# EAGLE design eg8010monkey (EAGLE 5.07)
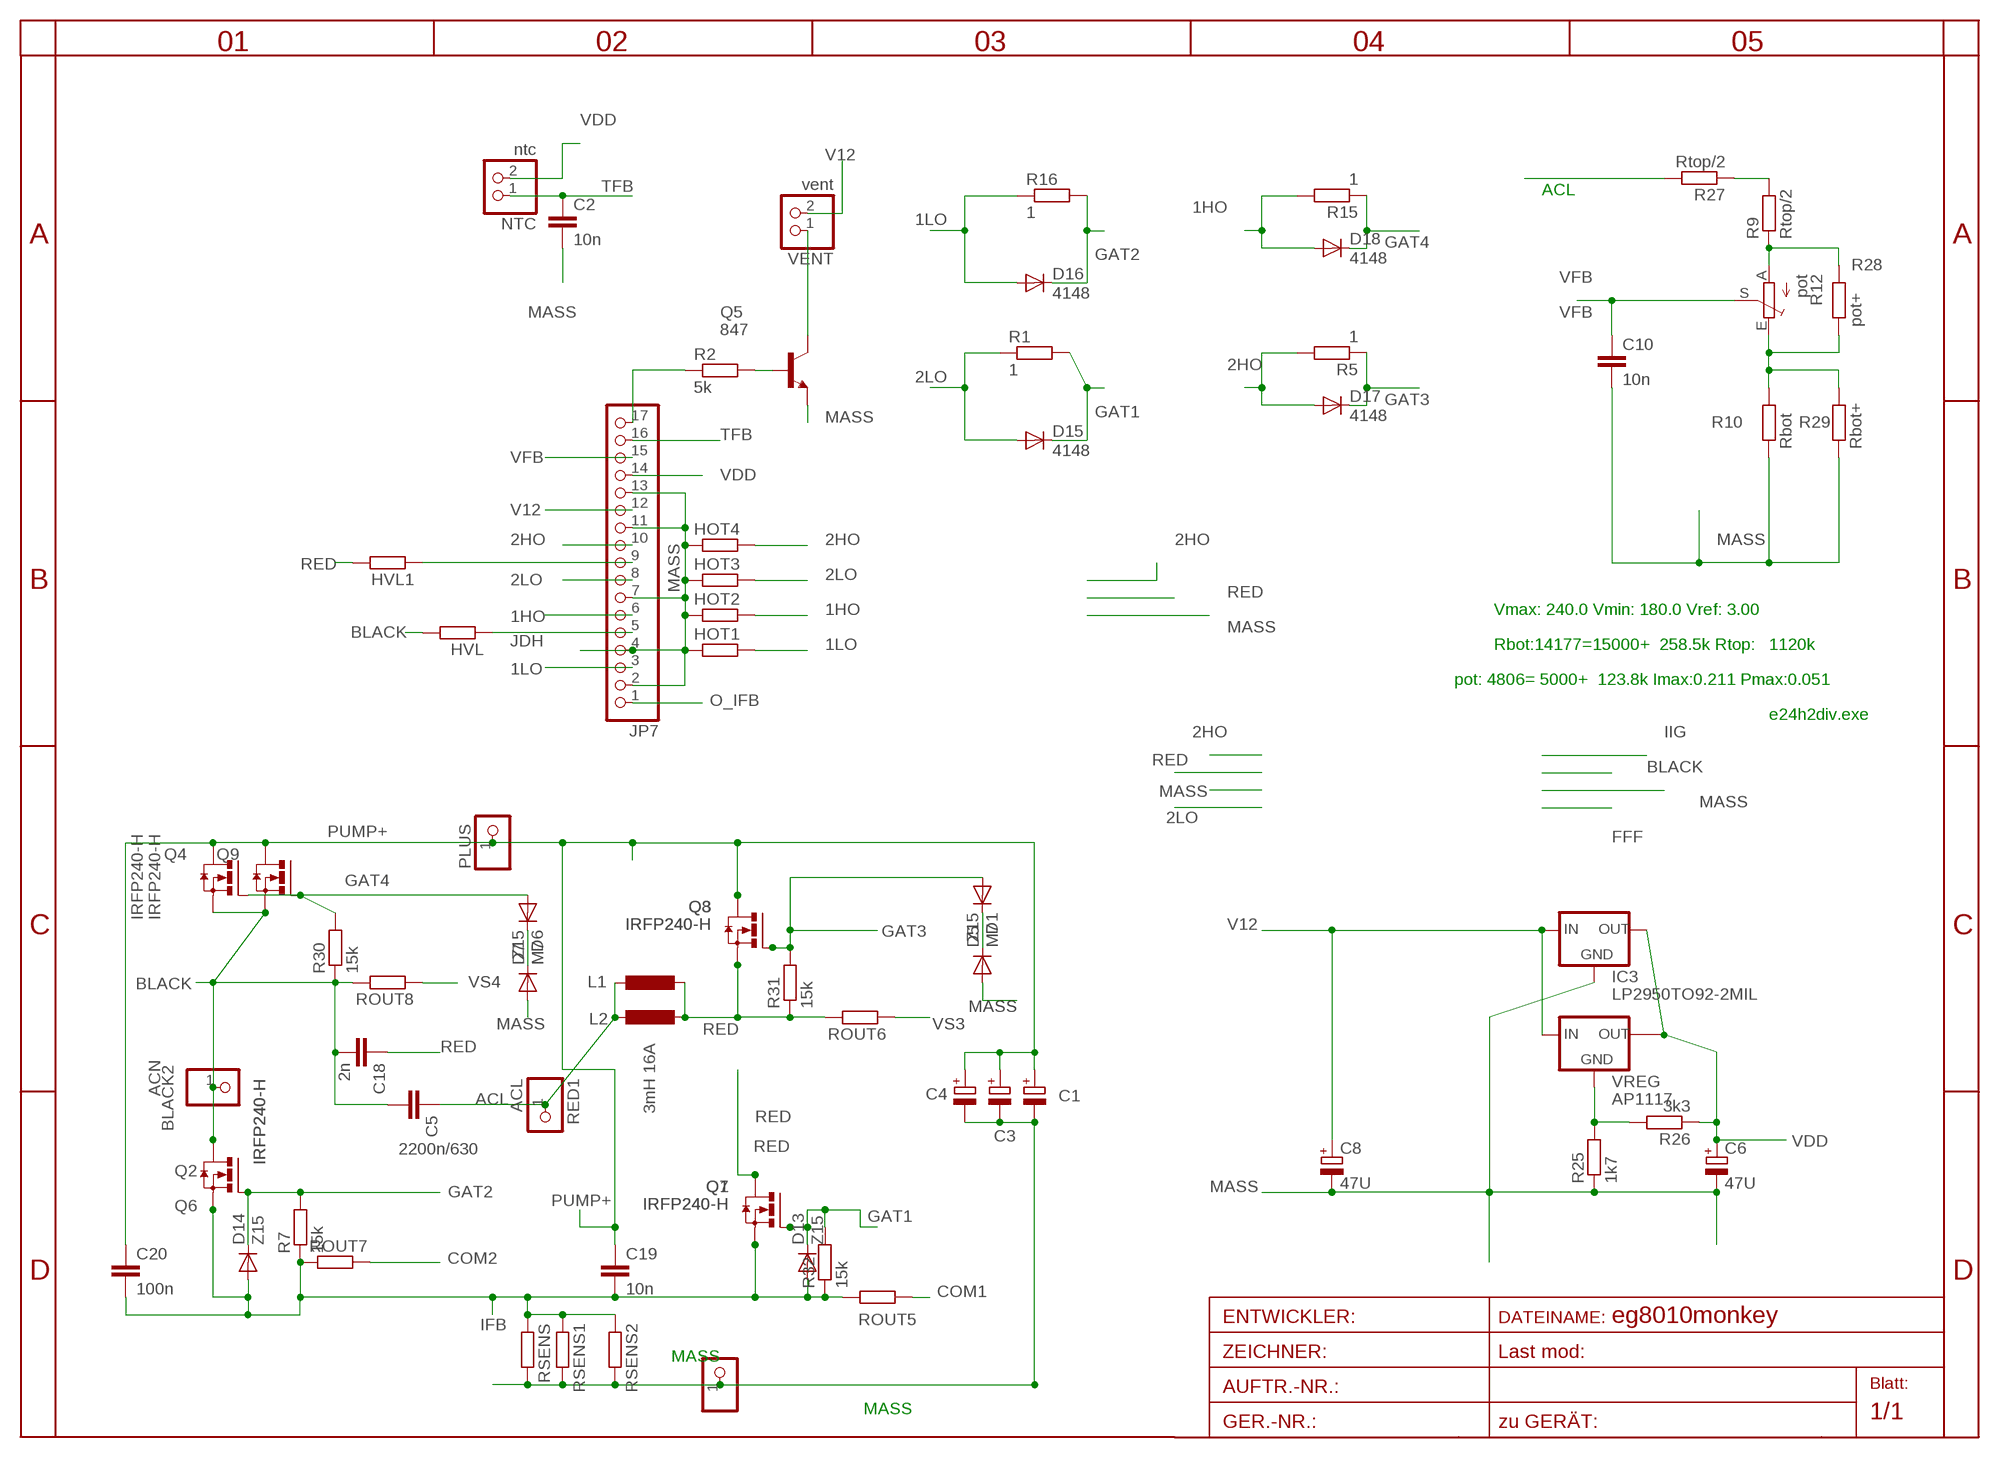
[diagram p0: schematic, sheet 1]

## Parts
BLACK2  ACN  PINHD-1X12MM3  [1X2MM3]
C1  CPOL-EUE5-13  [E5-13]
C2  10n  C-EUC0805  [C0805]
C3  CPOL-EUE5-13  [E5-13]
C4  CPOL-EUE5-13  [E5-13]
C5  2200n/630  C-EU275-173X316  [C275-173X316]
C6  47U  CPOL-EUSMCA  [SMC_A]
C8  47U  CPOL-EUSMCA  [SMC_A]
C10  10n  C-EUC0805  [C0805]
C18  2n  C-EU050-024X044  [C050-024X044]
C19  10n  C-EU050-024X044  [C050-024X044]
C20  100n  C-EU050-024X044  [C050-024X044]
D1  Z15  DIODE-MINIMELF  [MINIMELF]
D5  M7  DIODE-SMA-DO214  [SMA-DO214AC]
D6  Z15  DIODE-MINIMELF  [MINIMELF]
D7  M7  DIODE-SMA-DO214  [SMA-DO214AC]
D13  Z15  DIODE-MINIMELF  [MINIMELF]
D14  Z15  DIODE-MINIMELF  [MINIMELF]
D15  4148  DIODE-MINIMELF  [MINIMELF]
D16  4148  DIODE-MINIMELF  [MINIMELF]
D17  4148  DIODE-MINIMELF  [MINIMELF]
D18  4148  DIODE-MINIMELF  [MINIMELF]
HOT1  R-EU_R0805  [R0805]
HOT2  R-EU_R0805  [R0805]
HOT3  R-EU_R0805  [R0805]
HOT4  R-EU_R0805  [R0805]
HVL  R-EU_R1005  [R1005]
HVL1  R-EU_R1005  [R1005]
IC3  LP2950TO92-2MIL  [TO92-2MIL]
JP7  PINHD-1X17  [1X17]
L1  L-EU4.13  [0204/13]
L2  3mH 16A  L-EURNG  [RING]
MINUS  PINHD-1X12MM3  [1X2MM3]
NTC  ntc  PINHD-1X2STR  [1X02]
PLUS  PINHD-1X12MM3  [1X2MM3]
Q1  IRFP240-H  [TO247BH]
Q2  IRFP240-H  [TO247BH]
Q3  IRFP240-H  [TO247BH]
Q4  IRFP240-H  [TO247BH]
Q5  847  BC847SMD  [SOT23]
Q6  IRFP240-H  [TO247BH]
Q7  IRFP240-H  [TO247BH]
Q8  IRFP240-H  [TO247BH]
Q9  IRFP240-H  [TO247BH]
R1  1  R-EU_R2512  [R2512]
R2  5k  R-EU_R0805  [R0805]
R5  1  R-EU_R2512  [R2512]
R7  15k  R-EU_R1206  [R1206]
R9  Rtop/2  R-EU_R1206  [R1206]
R10  Rbot  R-EU_R0805  [R0805]
R12  pot  TRIM_EU-B64Y  [B64Y]
R15  1  R-EU_R2512  [R2512]
R16  1  R-EU_R2512  [R2512]
R25  1k7  R-EU_R0805  [R0805]
R26  3k3  R-EU_R0805  [R0805]
R27  Rtop/2  R-EU_R1206  [R1206]
R28  pot+  R-EU_R0805  [R0805]
R29  Rbot+  R-EU_R0805  [R0805]
R30  15k  R-EU_R1206  [R1206]
R31  15k  R-EU_R1206  [R1206]
R32  15k  R-EU_R1206  [R1206]
RED1  ACL  PINHD-1X12MM3  [1X2MM3]
ROUT5  R-EU_R2512  [R2512]
ROUT6  R-EU_R2512  [R2512]
ROUT7  R-EU_R2512  [R2512]
ROUT8  R-EU_R2512  [R2512]
RSENS  R-EU_WIRE  [WIRE]
RSENS1  R-EU_WIRE  [WIRE]
RSENS2  R-EU_WIRE  [WIRE]
VENT  vent  PINHD-1X2STR  [1X02]
VREG  AP1117  [SOT223]

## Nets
1HO: D18.A HOT2.2 JP7.6 R15.2
1LO: D16.A HOT1.2 JP7.3 R16.1
2HO: D17.A HOT4.2 JP7.10 R5.2
2LO: D15.A HOT3.2 JP7.8 R1.1
ACL: C5.1 L1.1 L2.2 R27.2 RED1.1
BLACK: BLACK2.1 C5.2 C18.2 HVL.2 Q2.D Q4.S Q6.D Q9.S R30.1 ROUT8.2
COM1: ROUT5.1
COM2: ROUT7.2
GAT1: D13.C D15.C Q1.G Q7.G R1.2 R32.2
GAT2: D14.C D16.C Q2.G Q6.G R7.2 R16.2
GAT3: D1.A D17.C Q3.G Q8.G R5.1 R31.2
GAT4: D6.A D18.C Q4.G Q9.G R15.1 R30.2
IFB: C19.2 C20.2 D13.A D14.A Q1.S Q2.S Q6.S Q7.S R7.1 R32.1 ROUT5.2 ROUT7.1 RSENS1.1 RSENS2.1 RSENS.1
JDH: HVL.1 JP7.5
MASS: C1.- C2.2 C3.- C4.- C6.- C8.- C10.2 D5.A D7.A HOT1.1 HOT2.1 HOT3.1 HOT4.1 IC3.2(GND) JP7.2 JP7.4 JP7.7 JP7.11 JP7.13 MINUS.1 Q5.2(E) R10.1 R25.1 R29.1 RSENS1.2 RSENS2.2 RSENS.2
N$1: Q5.3(C) VENT.1
N$2: Q5.1(B) R2.2
N$3: JP7.17 R2.1
N$17: R25.2 R26.2 VREG.1(GND)
N$20: D1.C D5.K(C)
N$23: R9.2 R27.1
N$24: D6.C D7.K(C)
N$29: R10.2 R12.E R28.1 R29.2
N$30: R9.1 R12.A R28.2
O_IFB: JP7.1
PUMP+: C1.+ C3.+ C4.+ C19.1 C20.1 PLUS.1 Q3.D Q4.D Q8.D Q9.D
RED: C18.1 HVL1.2 L1.2 L2.1 Q1.D Q3.S Q7.D Q8.S R31.1 ROUT6.2
TFB: C2.1 JP7.16 NTC.1
V12: C8.+ IC3.3(IN) JP7.12 VENT.2 VREG.3(IN)
VDD: C6.+ IC3.1(OUT) JP7.14 NTC.2 R26.1 VREG.4(TAB)
VFB: C10.1 JP7.15 R12.S
VS3: HVL1.1 JP7.9 ROUT6.1
VS4: ROUT8.1
Unconnected: VREG.2(OUT)

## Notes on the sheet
- Vmax: 240.0 Vmin: 180.0 Vref: 3.00
- Rbot:14177=15000+  258.5k Rtop:   1120k
- pot: 4806= 5000+  123.8k Imax:0.211 Pmax:0.051
- e24h2div.exe

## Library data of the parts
BLACK2 MINUS PLUS RED1 = pinhead:PINHD-1X1: PIN HEADER
C1 C3 C4 C6 C8 = rcl:CPOL-EU: POLARIZED CAPACITOR, European symbol
C2 C5 C10 C18-C20 = rcl:C-EU: CAPACITOR, European symbol
D1 D5-D7 D13-D18 = diode:DIODE-: DIODE
HOT1-HOT4 HVL HVL1 R1 R2 R5 R7 R15 R16 R30-R32 ROUT5-ROUT8 RSENS RSENS1 RSENS2 = rcl:R-EU_: RESISTOR, European symbol
IC3 = v-reg:LP2950?*: Source: http://cache.national.com/ds/LP/LP2950.pdf
JP7 = pinhead:PINHD-1X17: PIN HEADER
L1 L2 = rcl:L-EU: INDUCTOR, European symbol
NTC VENT = pinhead:PINHD-1X2: PIN HEADER
Q1-Q4 Q6-Q9 = transistor-power:IRFP240: HEXFET Power MosFet Source: http://www.irf.com/
Q5 = transistor-npn:BC847*: NPN Transistor
R9 R10 R25-R29 = rcl-2:R-EU_: RESISTOR, European symbol
R12 = pot:TRIM_EU-: POTENTIOMETER
VREG = v-reg:AP1117

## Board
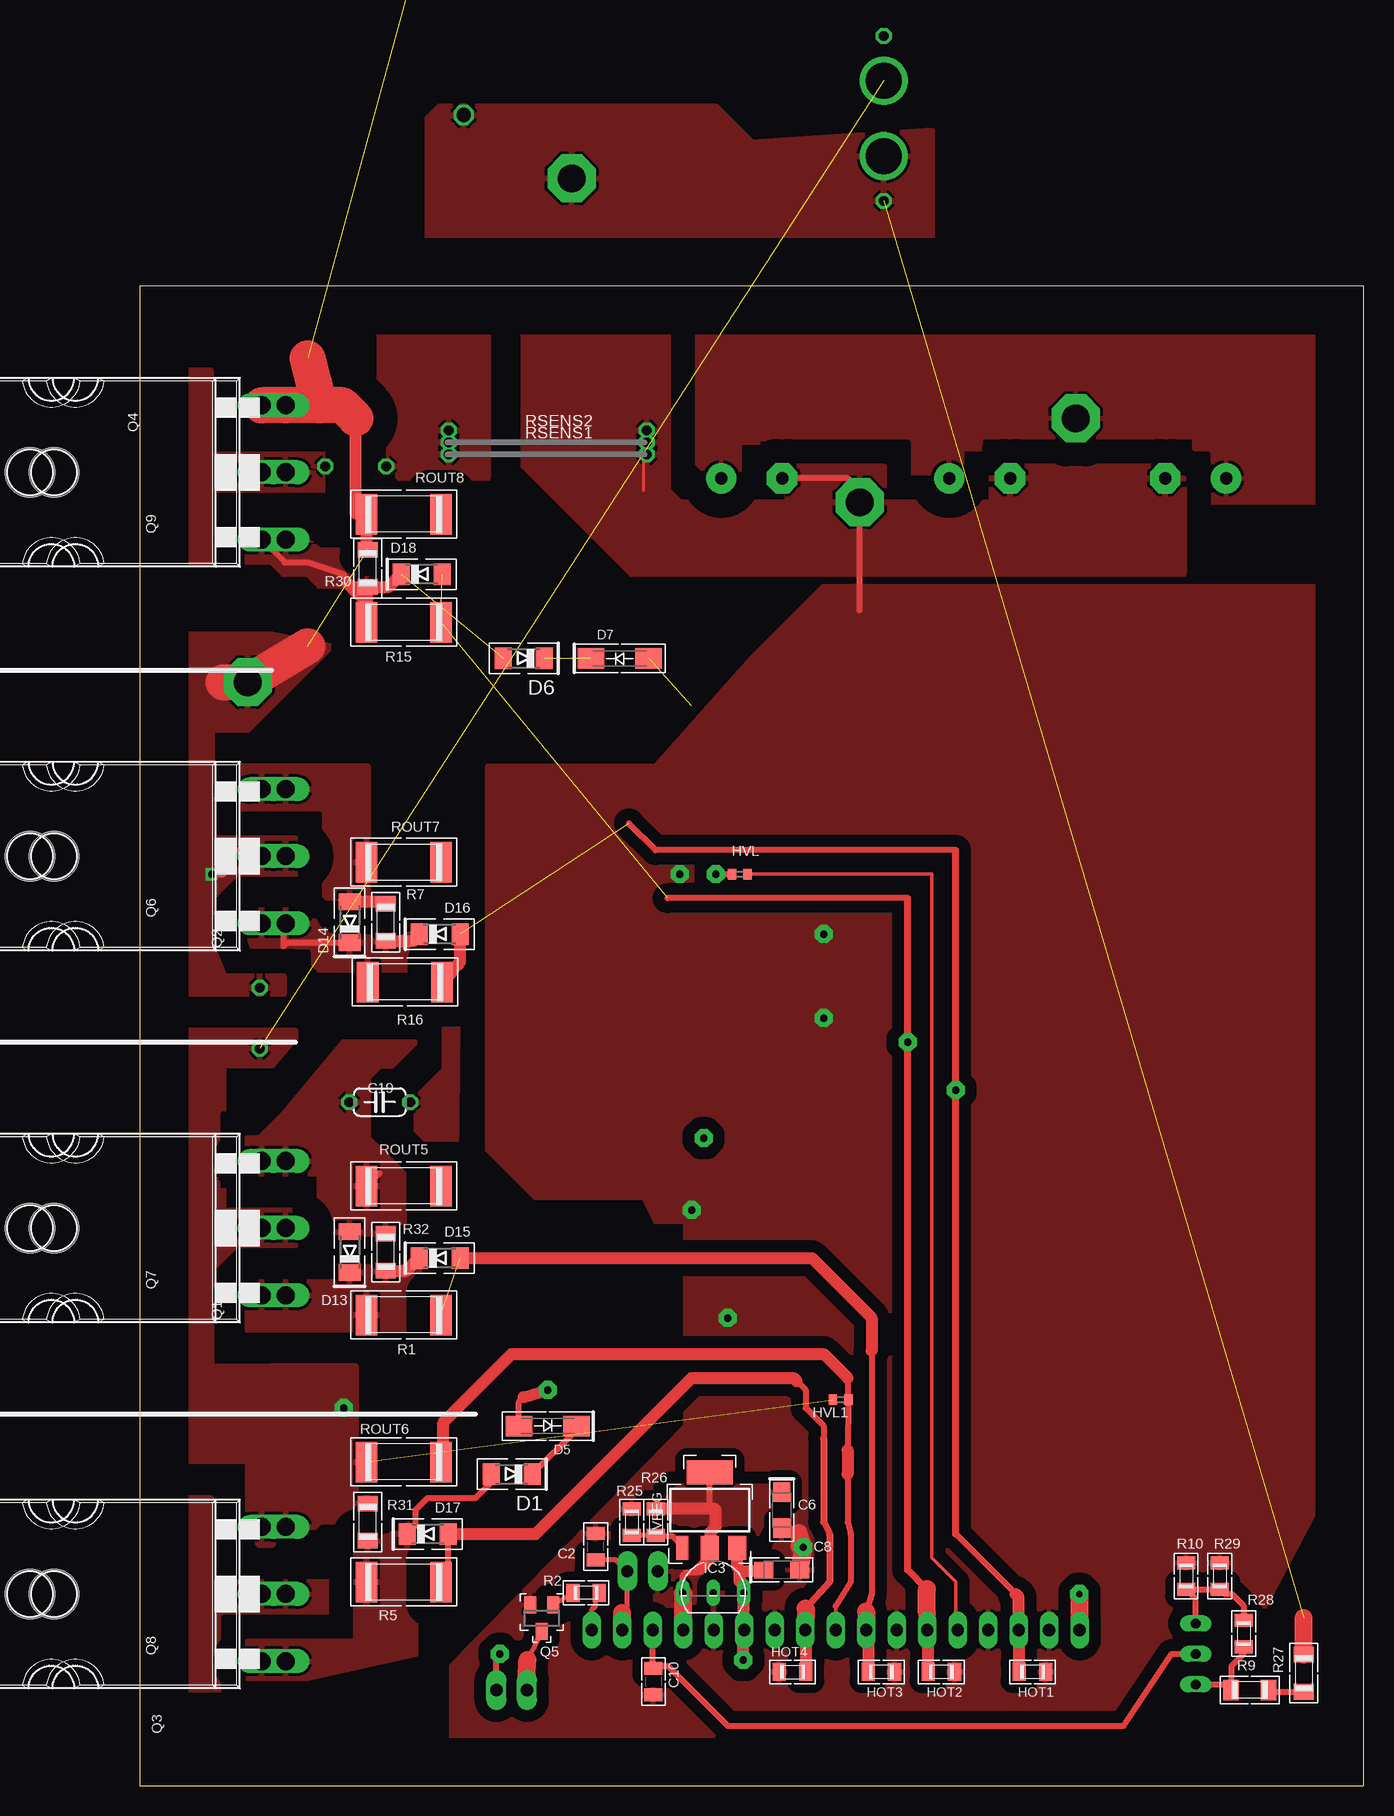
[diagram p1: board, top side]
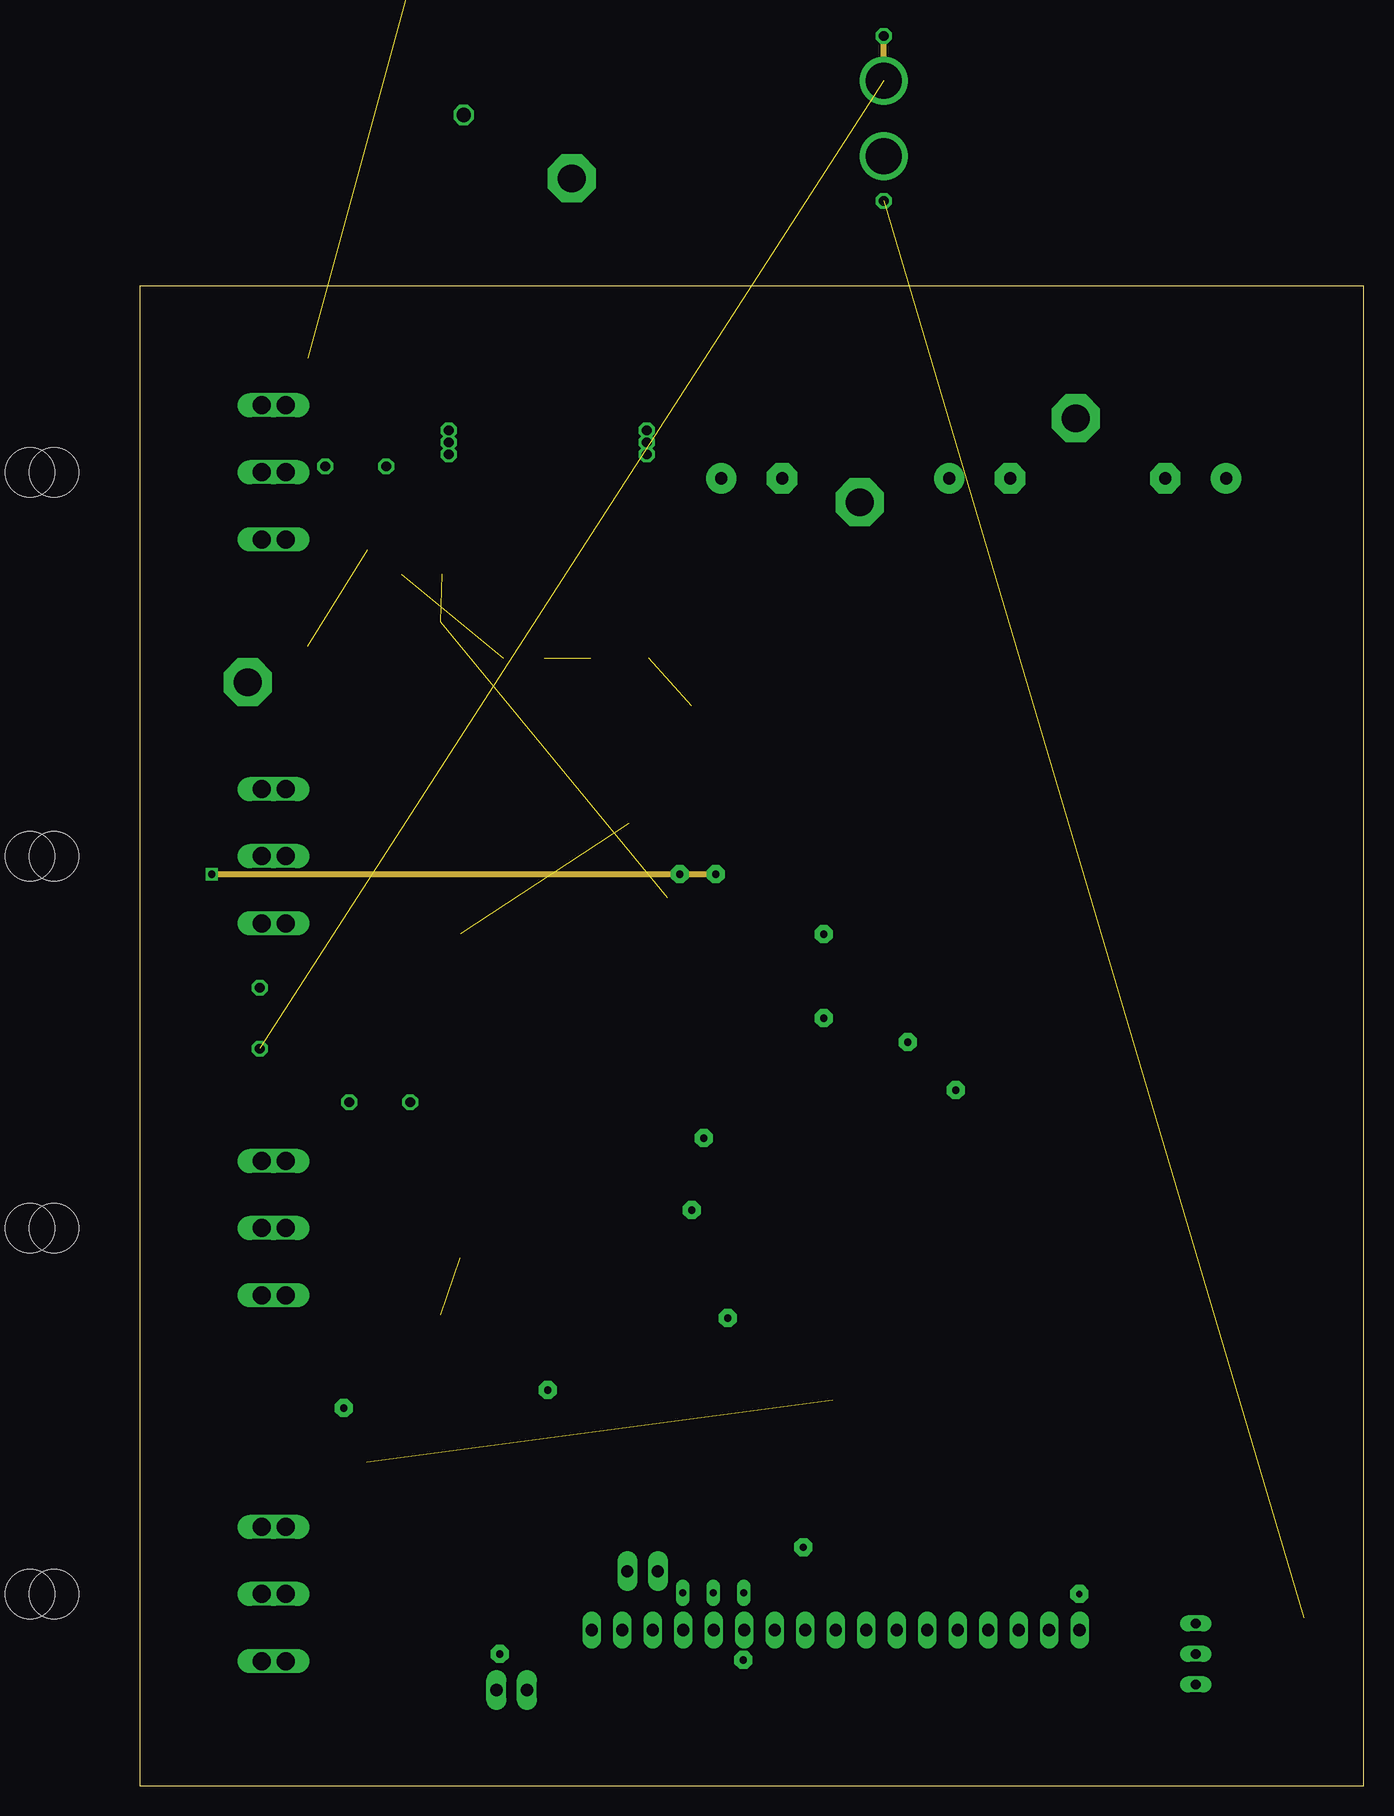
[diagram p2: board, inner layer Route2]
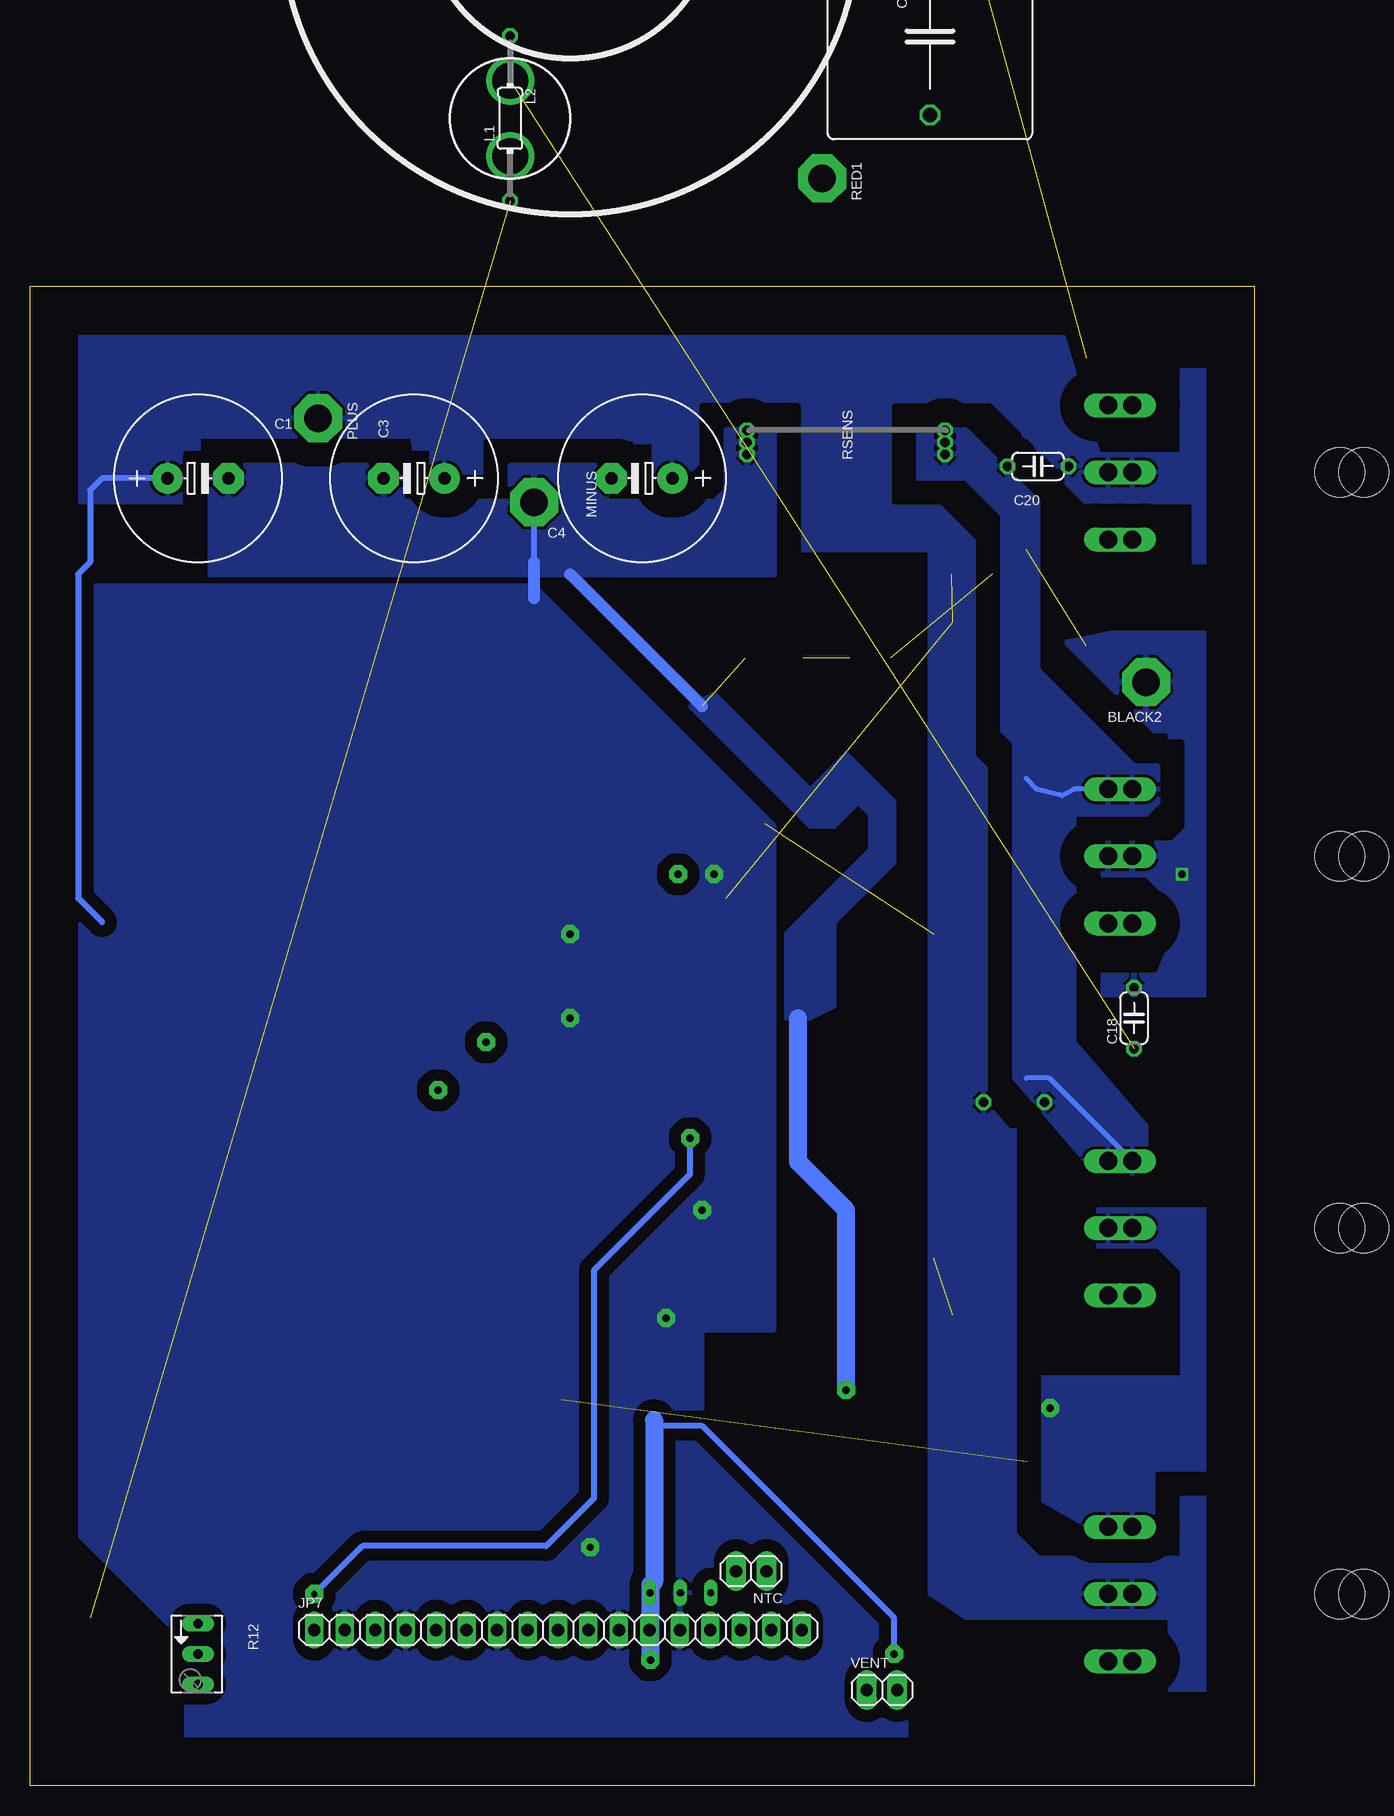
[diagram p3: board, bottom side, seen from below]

Size 102 x 125 mm. Coordinates in mm from the lower left corner, seen from the top.
Outline: 0,0 102,0 102,125 0,125 0,0
Copper layers (1*16): Top 0.035mm / dielectric 1.5mm / Bottom 0.035mm
Design rules "default *": minimum track width 10mil, minimum drill 20mil, track to track 8mil, track to pad 8mil, pad to pad 8mil, via to via 8mil, smd to smd 8mil, copper to edge 4mm, drill to drill 8mil, minimum pad ring 10mil, minimum via ring 8mil, stop-mask expansion 4mil, vias tented up to drill 0mil, thermal gap 10mil

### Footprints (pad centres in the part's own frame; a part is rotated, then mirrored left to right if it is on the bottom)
1X2MM3 = drill 2.3 pad 4 octagon: 1 0,0
E5-13 = drill 1.016 pad 2.54 round: + -2.54,0 | drill 1.016 pad 2.54 octagon: - 2.54,0
C0805 = smd 1.1 x 1.5: 1 -1.1,0; 2 1.1,0
C275-173X316 = drill 1.194 octagon: 1 -13.716,0; 2 13.716,0
SMC_A = smd 1.6 x 1.4: + -1.5,0; - 1.5,0
C050-024X044 = drill 0.813 octagon: 1 -2.54,0; 2 2.54,0
MINIMELF = smd 1.4 x 1.8: A 1.7,0; C -1.7,0
SMA-DO214AC = smd 2.2 x 1.7: A 2.4,0; K -2.4,0
R0805 = smd 1.1 x 1.5: 1 -1.1,0; 2 1.1,0
R1005 = smd 0.7 x 0.9: 1 -0.65,0; 2 0.65,0
TO92-2MIL = drill 0.6 pad 0.813 long: 1 -2.54,0; 2 0,0; 3 2.54,0
1X17 = drill 1.016 long: 1 -20.32,0; 2 -17.78,0; 3 -15.24,0; 4 -12.7,0; 5 -10.16,0; 6 -7.62,0; 7 -5.08,0; 8 -2.54,0; 9 0,0; 10 2.54,0; 11 5.08,0; 12 7.62,0; 13 10.16,0; 14 12.7,0; 15 15.24,0; 16 17.78,0; 17 20.32,0
0204/13 = drill 0.813 octagon: 1 -6.872,0; 2 6.872,0
RING = drill 3 pad 4 round: 1 -3.15,0; 2 3.15,0
1X02 = drill 1.016 pad 1.676 long: 1 -1.27,0; 2 1.27,0
TO247BH = drill 1.499 long: D 0,-10.16; G -5.588,-10.16; S 5.588,-10.16 | hole 4.115: 0,9.144
SOT23 = smd 1 x 1.4: 1 -0.95,-1.1; 2 0.95,-1.1; 3 0,1.1
R2512 = smd 1.8 x 3.4: 1 -3.1,0; 2 3.1,0
R1206 = smd 1.3 x 1.7: 1 -1.55,0; 2 1.55,0
B64Y = drill 0.813 long: A 2.54,0; E -2.54,0; S 0,0
WIRE = drill 0.813 octagon: 1 -8.25,0; 2 8.25,0
SOT223 = smd 1 x 2: 1 -2.3,-3.15 | smd 1.5 x 2: 2 0,-3.15; 3 2.3,-3.15 | smd 3.8 x 2: 4 0,3.15

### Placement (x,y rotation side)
BLACK2  9,92 180 bottom
C1  88,109 0 bottom
C2  38,19.95 90 top
C3  70,109 180 bottom
C4  51,109 180 bottom
C5  not placed on the board
C6  53.5,23 270 top
C8  53.5,18 0 top
C10  42.8,8.7 270 top
C18  10,64 90 bottom
C19  20,57 180 top
C20  18,110 180 bottom
D1  31,26 180 top
D5  34,30 180 top
D6  32,94 180 top
D7  40,94 0 top
D13  17.5,44.5 90 top
D14  17.5,72 90 top
D15  25,44 0 top
D16  25,71 0 top
D17  24,21 0 top
D18  23.5,101 0 top
HOT1  74.4,9.5 180 top
HOT2  66.8,9.5 180 top
HOT3  61.8,9.5 180 top
HOT4  54.4,9.5 0 top
HVL  50,76 180 top
HVL1  58.4,32.2 180 top
IC3  47.8,16.1 0 top
JP7  58,13 0 bottom
L1  62,139 90 bottom  (outside the outline)
L2  62,139 270 bottom  (outside the outline)
MINUS  60,107 270 bottom
NTC  41.9,17.9 180 bottom
PLUS  78,114 270 bottom
Q1  0,46.5 90 top
Q2  0,77.5 90 top
Q3  0,16 90 top
Q4  0,109.5 90 top
Q5  33.5,14 180 top
Q6  2,77.5 90 top
Q7  2,46.5 90 top
Q8  2,16 90 top
Q9  2,109.5 90 top
R1  22,39.25 180 top
R2  37.2,16.1 180 top
R5  22,17 0 top
R7  20.5,72 270 top
R9  92.5,8 0 top
R10  87.2,17.5 270 top
R12  88,11 270 bottom
R15  22,97 0 top
R16  22.1,67 180 top
R25  41,22 270 top
R26  43,22 270 top
R27  97,9.4 90 top
R28  92,12.7 270 top
R29  90,17.5 270 top
R30  19,101.5 270 top
R31  19,22 270 top
R32  20.5,44.5 270 top
RED1  not placed on the board
ROUT5  22,50 180 top
ROUT6  22,27 180 top
ROUT7  22,77 0 top
ROUT8  22,106 180 top
RSENS  34,113 180 bottom
RSENS1  34,111 0 top
RSENS2  34,112 0 top
VENT  31,8 0 bottom
VREG  47.5,23 0 top

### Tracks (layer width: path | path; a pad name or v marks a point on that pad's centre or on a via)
1HO  (via drill 0.6 pad 1.5)  (2 unrouted)
  Top 0.5: 64,74 44,74
  Top 0.6: 65.6,16.4 64,18 v64,62 64,74
  Top 1: 65.6,14.4 JP7.6 65.7,12.92 HOT2.2
  Top 1.5: 65.6,14.4 65.6,16.4
1LO  (via drill 0.6 pad 1.5)  (1 unrouted)
  Top 0.5: 68,78 43,78 40.77,80.23 | 73,16 68,21
  Top 0.6: 68,21 v68,58 68,78
  Top 1: 73,16 73.24,15.76 JP7.3 73.3,12.94 HOT1.2 | D16.A 26.7,68.7 26,68 26,67.8 R16.1
2HO
  Top 0.5: 57,29 57,30 55.5,31.5 55.5,33 54.75,33.75 | D17.A 25.7,17.6 R5.2
  Top 0.6: 55.5,14.8 57.5,17 57.5,21 57,22 57,29
  Top 1: HOT4.2 55.5,12.96 JP7.10 | D17.A 33,21 46,34 54.5,34 54.75,33.75
  Top 1.5: 55.5,14.8 JP7.10
2LO  (1 unrouted)
  Top 0.5: 60.54,14.54 61,16 61,36.27
  Top 1: HOT3.2 60.7,12.84 JP7.8 | D15.A 56,44 61,39 61,36.27
  Top 1.5: 60.54,14.54 JP7.8
ACL  (1 unrouted)
  Top 1.5: R27.2 97,14
  pour Top: 66,138 66,129 24,129 24,139 25,140 48,140 51,137
BLACK  (via drill 0.6, 0.6 pad 1.5)  (2 unrouted)
  Top 0.5: v48,76 HVL.2 | v6,76 7,76 7,78 11,78
  Top 1: 18,114 18,106.1 ROUT8.2 18.9,103.15 R30.1
  Top 3: 15,115.09 16.91,115.09 18,114 | 15,115.09 Q9.S Q4.S | 14,95 BLACK2.1 7,92 | 15,115.09 14,119
  Route2 0.5: v6,76 v48,76
  pour Top (isolate 2): 16,95 9,88 6,88 6,79 13,79 13,76 8,76 6,74 6,70 7,67.5 12,67.5 12,66 3,66 3,96 11,96
  pour Bottom (isolate 2, rank 5): 17,95 10,88 7,88 7,79 14,79 14,76 9,76 7,74 7,70 8,67.5 13,67.5 13,66 4,66 4,96 12,96
GAT1
  Top 1: R32.2 22.25,42.95 D15.C
  pour Top (isolate 2): 9,42 17,42 17,44 24,44 22,38 9,38
GAT2
  Top 0.5: D14.C 12.3,70.3 12,70 12,72 12.07,72 Q6.G
  Top 1: R7.2 22.85,70.45 D16.C
  pour Top (isolate 2, rank 2): 8,73 14,73 21,71 24,71 24,68 15,68 13,70 8,70
GAT3
  Top 0.5: D1.A 29.3,25.3 28,24 24,24 23,23 23,21.7 D17.C
  pour Top (isolate 2, rank 3): 9,12 9,9 14,9 23,11 23,22 18,20 18,12
GAT4  (1 unrouted)
  Top 0.5: Q4.G 12.07,102 14,102 17,101 17.39,100.18
  Top 1: 17.62,99.95 R30.2 20.75,99.95 D18.C | 17.39,100.18 17.62,99.95 | R15.1 18.9,98.9 19,99 18.57,99 17.62,99.95
  pour Top (isolate 1.5): 8.9,104.5 12.9,104.5 15,103 18,103 19,102 19,101 18,100 15,100 14,101 12,101 11,102 9,102
IFB
  Top 0.5: ROUT5.2 20,51.1
  Top 1: D14.A 20.35,73.7 R7.1
  Bottom 0.406: 19,84 18.08,83.08 16,82.55 14.99,83.09 Q2.S | Q1.S 17.07,59 19,59
  pour Bottom (isolate 2): 28,113 28,109 24,109 21,106 21,88 20,87 20,59 14,52 10,51 9,52 9,55 15,62 15,81 9,81 8,82 8,85 10,85 18,93 18,107 24,113
  pour Top (isolate 2, rank 2): 20,121 29,121 29,109 20,109
  pour Top (isolate 2, rank 2): 9,51 9,54 10,54 12,56 17,62 23,62 21,60 20,60 19,59 19,54 22,51 22,46 15,46 15,51
  pour Top (isolate 2, rank 2): 8,85 19,85 19,74 14,74 14,81 8,81
JDH
  Top 0.3: HVL.1 66,76 66,19 68,17 68,13.16 JP7.5
MASS  (via drill 0.6 pad 1.5)  (1 unrouted)
  Top 0.254: 42,110 42,112 | C4.- 53,109 | 42,108 42,110 | 42,110 RSENS.2
  Top 0.5: C4.- 59,109 60,108 60,98 | D5.A 31.6,32 32,32.4
  Top 1: 32,32.4 v34,33
  Top 1.5: v55.3,19.9 54.9,21.1 | C8.- 55.3,19.7 55,20
  Bottom 0.5: 60,102 MINUS.1
  Bottom 1: 46,90 57,101 | 60,99 60,102
  Bottom 1.5: v34,33 34,48 38,52 38,64
  other vias: 49,39 57,64 57,71 46,48 45,76
  pour Bottom (isolate 2): 96,97 96,73 73,73 73,97
  pour Bottom (isolate 1, rank 4): 40,80 60,100 99,100 99,22 89,12 89,4 29,4 29,14 44,28 46,30 46,38 40,38
  pour Top (isolate 1, rank 4): 51,94 57,100 100,100 98,23 88,4 26,4 26,10 45.5,30 45.5,47 43,47 42,49 33,49 29,53 29,85 43,85
  pour Bottom (isolate 2, rank 2): 40,113 44,113 44,108 45,107 54,107 54,110 62,110 62,107 71,107 71,110 86,110 87,109 87,101 40,101
  pour Top (isolate 2, rank 2): 32,121 44,121 44,108 45,107 54,107 54,110 62,110 62,107 71,107 71,110 86,110 87,109 87,101 41,101 32,110
  pour Bottom (isolate 1.5): 45,91 47,90 37,80 35,80 33,82 32,81 32,78 39,71 39,64 37,64 35,65 35,72 30,77 30,82 34,86 37,83
N$1
  Top 0.406: VENT.1 32.27,8.97 | 32.3,10.5 33,11.8 Q5.3
  Top 1.5: 32.27,8.97 32.3,10.5
N$2
  Top 0.406: Q5.1 R2.2
N$3
  Top 0.406: JP7.17 37.68,14.68 38,15 38,15.8 R2.1
N$17
  Top 0.406: R26.2 R25.2
  Top 0.5: VREG.1 45.2,20 44.4,20.8 43.1,20.8 R26.2
N$20
  Top 0.5: D5.K 36.4,29.7 D1.C
N$23
  Top 0.5: R27.1 94.2,7.85 R9.2
N$24  (1 unrouted)
N$29
  Top 0.5: R28.1 92,15 91,16 90.4,16 R29.2 R10.2 88,15.6 R12.E
N$30
  Top 0.5: R12.A 90.49,8.46 R9.1 91,8.05 91,10 92,11 R28.2
O_IFB  (via drill 0.51 pad 1.5, 0.6 pad 1.5)
  Top 0.254: 78.3,14 JP7.1
  Top 1.5: v78.3,16 78.3,14
  Bottom 0.5: v78.3,16 74.3,20 59,20 55,24 55,43 47,51 v47,54
PUMP+
  Bottom 0.5: C1.+ 96,109 97,108 97,102 98,101 98,74 96,72
  pour Bottom (isolate 2, rank 3): -16,24 -16,8 7,8 7,14 24,14 27,16 27,103 40,103 40,113 44,113 45,112 45,109 50,109 50,112 64,112 64,108 65,107 70,107 70,112 86,112 89,109 89,107 98,107 98,121 16,121 13,111 6,111 6,118 -17,118 -17,102 5,102 5,107 14,107 19,112 29,112 29,108 22,108 20,105 20,21 18,19 6,19 6,24
  pour Top (isolate 2, rank 4): 3,24 3,8 7,8 7,14 24,14 26,16 27,103 39,103 39,113 44,113 45,112 45,109 50,109 50,112 64,112 64,108 65,107 70,107 70,112 86,112 89,109 89,107 99,107 99,121 32,121 32,111 6,111 6,118 1,118 1,102 6,102 6,108 23,108 23,21 18,17 6,17 6,24
RED  (via drill 0.6 pad 1.5)  (2 unrouted)
  Route2 0.5: L2.1 L1.2
  other vias: 17,31.5
  pour Bottom (isolate 2, rank 4): 2,48 13,48 13,45 8,45 6,43 6,34 18,34 18,24 11,20 10,20 9,21 2,27
  pour Top (isolate 2): 10,23 11,35 18,35 18,24 19,24 17,22 15,22 14,21 10,21
  pour Top (isolate 2, rank 3): 1,63 13,63 13,60 7,60 7,48 13,48 13,45 8,45 6,43 6,35 12,35 12,21 11,20 10,20 9,21 9,27 1,27
TFB
  Top 0.406: C2.1 39.68,18.85 NTC.1 40.63,15.03 40.2,14.4 | JP7.16 40.2,13.22
  Top 1.5: 40.2,13.22 40.2,14.4
V12  (via drill 0.6 pad 1.5)
  Top 0.406: JP7.12 50.2,13.18
  Top 0.5: 50.3,12.92 JP7.12 | VENT.2 29.73,10.73 v30,11
  Top 1: v50.3,10.5 50.3,12.92 | 50.34,13.04 IC3.3 50.3,16.14 50.3,16.8 50,17.1 50,18 | VREG.3 49.8,18.2 50,18 | C8.+ 50.1,17.9 50,18
  Top 1.5: JP7.12 50.34,13.04
  Bottom 0.5: 50,17 50.1,17 50.3,16.8 | 50,30.5 49.68,30.6 50,30.6 49.4,30 46,30 30,14 v30,11
  Bottom 1.5: 50.3,16.8 v50.3,10.5 | 50,30.5 50,17
VDD
  Top 0.5: IC3.1 45.26,17.56 45.5,17.8 46.4,17.8 46.7,18.1 | VREG.4 47.5,23.5 47.9,23.1
  Top 1: R26.1 47.9,23.1 48,23 48,21.6 47.6,21.2 47.6,19 46.7,18.1
  Top 1.5: JP7.14 45.3,16.06 IC3.1
  pour Top (isolate 0.8): 45,25 53,25 53,24 51,20 49,20 49,19 46,15 43,15 43,23
VFB
  Top 0.5: R12.S 86,11 82,5 49,5 44,10 43,10 C10.1 42.76,9.84 JP7.15
VS3
  Top 0.3: 58,15 JP7.9
  Top 0.5: ROUT6.1 25.3,28.51 | 59,26 59,22 59.25,21 59.25,17 58,15 | 59,28 HVL1.1 59,32.25 59,34
  Top 1: 25.3,28.51 25.3,30.3 31,36 57,36 59,34 | 59,28 59,26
